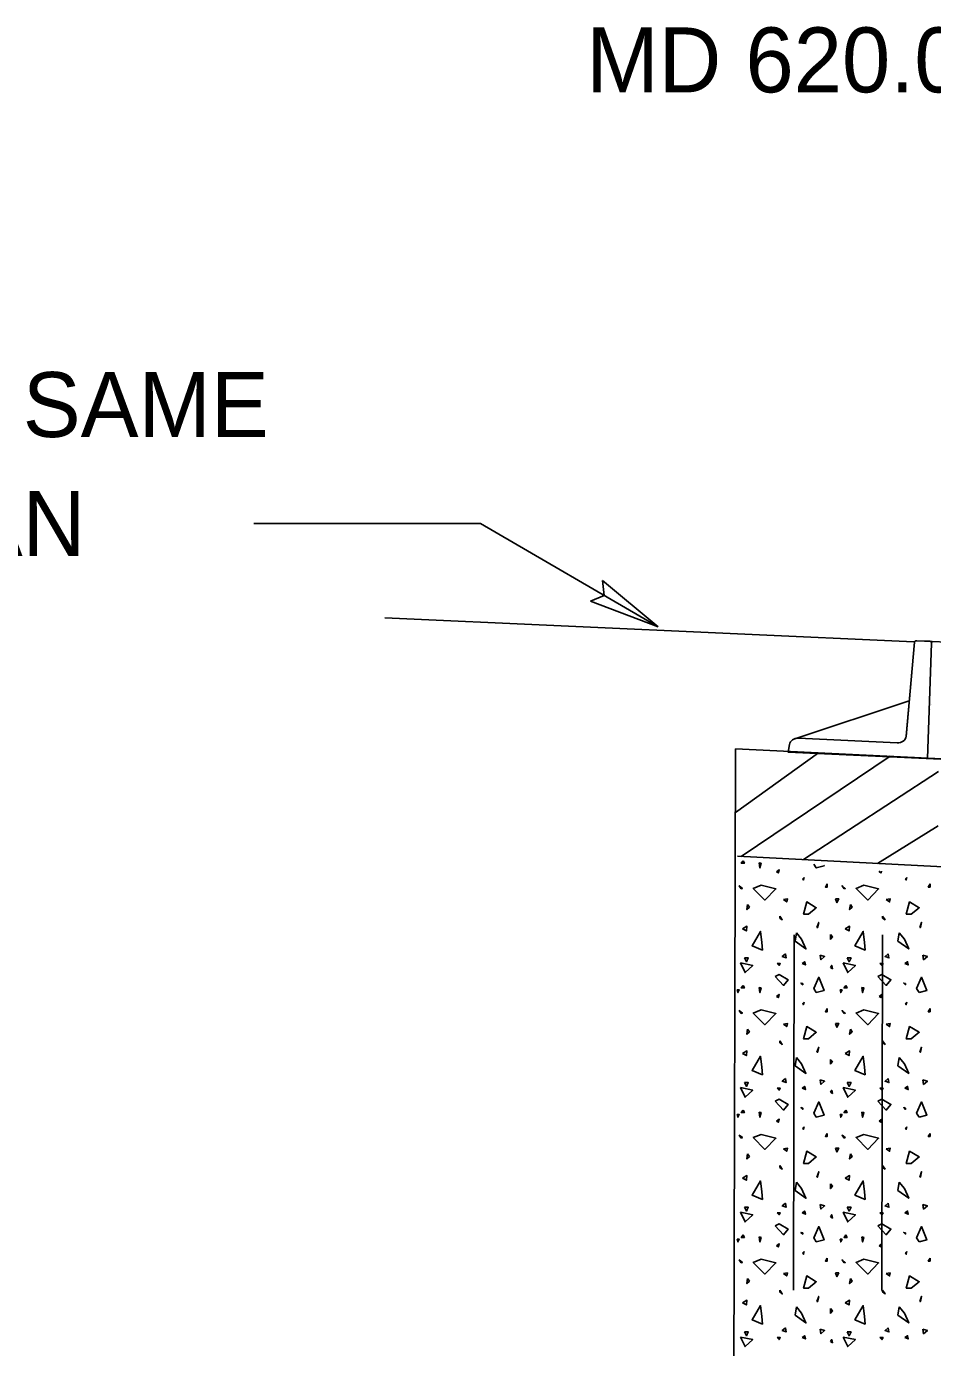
# Model space of a CAD drawing. Extents: x 9.6 to 16.8, y 2.2 to 12.2.
# Drawn here: x 14.196 to 15.034, y 8.202 to 9.423 of the extents above; entities that cross this region are included whole.
import ezdxf

# ---------------------------------------------------------------- set-up
doc = ezdxf.new("R2010")
doc.units = 0
for name, color, linetype in [('DETL-DIMS', 7, 'Continuous'), ('DETL-LINE', 7, 'Continuous'), ('DETL-NOTE', 7, 'Continuous'), ('DETL-PATT', 7, 'Continuous')]:
    doc.layers.add(name, color=color, linetype=linetype)

msp = doc.modelspace()

# ---------------------------------------------------------------- linework, layer by layer
at = {"layer": 'DETL-DIMS'}
for p, q in [((14.6158, 8.9636), (14.4063, 8.9636)), ((14.6158, 8.9636), (14.7799, 8.8683)), ((14.7285, 8.9109), (14.7799, 8.8683)), ((14.7285, 8.9109), (14.7301, 8.8973)), ((14.7175, 8.8919), (14.7301, 8.8973)), ((14.7175, 8.8919), (14.7799, 8.8683))]:
    msp.add_line(p, q, dxfattribs=at)
at = {"layer": 'DETL-LINE'}
for p, q in [((14.5274, 8.8764), (15.0164, 8.8545)), ((15.0169, 8.8539), (15.0092, 8.7671)), ((15.0169, 8.8539), (15.0092, 8.767)), ((15.031, 8.8549), (15.019, 8.8554)), ((15.019, 8.8554), (16.0453, 8.8081)), ((15.0289, 8.7466), (15.0328, 8.8532)), ((15.0121, 8.7999), (14.9062, 8.7648)), ((15.0009, 8.761), (14.9096, 8.7652)), ((15.0009, 8.761), (14.9096, 8.7652)), ((14.8516, 8.7556), (14.847, 6.99)), ((14.8516, 8.7556), (16.1474, 8.6923)), ((14.9001, 8.7525), (14.9013, 8.7596)), ((14.9001, 8.7525), (16.0729, 8.6984)), ((14.8533, 8.6562), (16.1526, 8.5894)), ((14.9058, 8.5837), (14.905, 8.2553)), ((14.9875, 8.5835), (14.9866, 8.2551))]:
    msp.add_line(p, q, dxfattribs=at)
msp.add_lwpolyline([(14.9013, 8.7596), (14.9001, 8.7525), (15.0289, 8.7466), (15.0328, 8.8532)], dxfattribs=at)
for centre, major_axis, start_param, end_param in [((15.0189, 8.8538), (0.00198, -0.00001), 1.521987, 3.073416), ((15.0189, 8.8538), (0.00198, -0.00001), 1.521987, 3.073416), ((15.0309, 8.8532), (0.00198, -0.00001), 6.257027, 7.805172), ((15.0309, 8.8532), (0.00198, -0.00001), 6.257027, 7.805172), ((14.9092, 8.7587), (0.00794, -0.00005), 1.521882, 3.005517), ((14.9092, 8.7587), (0.00794, -0.00005), 1.521987, 3.005517), ((15.0013, 8.7676), (0.00794, -0.00005), 4.663474, 6.226805), ((15.0013, 8.7676), (0.00794, -0.00005), 4.663579, 6.203213)]:
    msp.add_ellipse(centre, major_axis=major_axis, ratio=0.826446, start_param=start_param, end_param=end_param, dxfattribs=at)
at = {"layer": 'DETL-NOTE'}
for p, q in [((15.0318, 8.792), (15.0318, 8.792)), ((15.0331, 8.7967), (15.0331, 8.7967)), ((14.9001, 8.7525), (14.9001, 8.7525)), ((15.0289, 8.7466), (15.0289, 8.7466))]:
    msp.add_line(p, q, dxfattribs=at)
at = {"layer": 'DETL-PATT'}
for p, q in [((14.9282, 8.7519), (14.8515, 8.6967)), ((14.8567, 8.6561), (14.9946, 8.7486)), ((15.039, 8.7345), (14.9144, 8.6531)), ((14.9829, 8.6496), (15.0389, 8.6842))]:
    msp.add_line(p, q, dxfattribs=at)
for points in [[(14.8585, 8.6521), (14.8598, 8.6497), (14.8568, 8.6497)], [(14.8733, 8.6503), (14.874, 8.6455), (14.8751, 8.6497)], [(14.8894, 8.6419), (14.8911, 8.6408), (14.8918, 8.6438)], [(14.9149, 8.6365), (14.9137, 8.6355), (14.9144, 8.6342)], [(15.01, 8.6365), (15.0087, 8.6355), (15.0094, 8.6342)], [(14.8568, 8.626), (14.8579, 8.6265), (14.8549, 8.6289)], [(14.8751, 8.6295), (14.8888, 8.626), (14.8787, 8.6158), (14.8679, 8.6265)], [(14.9363, 8.6306), (14.9346, 8.6277), (14.9363, 8.6277)], [(14.9518, 8.626), (14.9529, 8.6265), (14.95, 8.6289)], [(14.9702, 8.6295), (14.9838, 8.626), (14.9737, 8.6158), (14.9629, 8.6265)], [(15.0313, 8.6306), (15.0296, 8.6277), (15.0313, 8.6277)], [(14.8627, 8.6117), (14.862, 8.6069), (14.8644, 8.6093)], [(14.8959, 8.6164), (14.8989, 8.614), (14.8994, 8.6169)], [(14.9191, 8.6027), (14.9262, 8.6087), (14.9173, 8.614), (14.9144, 8.6027)], [(14.944, 8.6169), (14.9452, 8.6134), (14.947, 8.6169)], [(14.9577, 8.6117), (14.957, 8.6069), (14.9594, 8.6093)], [(14.9909, 8.6164), (14.9939, 8.614), (14.9944, 8.6169)], [(15.014, 8.6027), (15.0213, 8.6087), (15.0124, 8.614), (15.0094, 8.6027)], [(14.8924, 8.601), (14.8924, 8.5991), (14.8947, 8.5975)], [(14.9268, 8.5903), (14.9274, 8.5903), (14.9285, 8.5951)], [(14.9874, 8.601), (14.9874, 8.5991), (14.9898, 8.5975)], [(15.0218, 8.5903), (15.0224, 8.5903), (15.0235, 8.5951)], [(14.8579, 8.5891), (14.8615, 8.5873), (14.862, 8.5915)], [(14.8757, 8.5765), (14.8763, 8.5695), (14.8668, 8.5736), (14.8746, 8.5867)], [(14.9078, 8.5855), (14.9066, 8.5778), (14.9166, 8.5706), (14.9125, 8.5795)], [(14.9392, 8.5838), (14.9392, 8.5795), (14.9411, 8.5819)], [(14.9529, 8.5891), (14.9565, 8.5873), (14.957, 8.5915)], [(14.9707, 8.5765), (14.9713, 8.5695), (14.9618, 8.5736), (14.9696, 8.5867)], [(15.0027, 8.5855), (15.0016, 8.5778), (15.0116, 8.5706), (15.0076, 8.5795)], [(14.8561, 8.5576), (14.8603, 8.5487), (14.8674, 8.5553)], [(14.8598, 8.5623), (14.8615, 8.5588), (14.8633, 8.5623)], [(14.8977, 8.566), (14.8947, 8.5636), (14.8983, 8.5623)], [(14.9131, 8.5571), (14.9161, 8.5558), (14.9155, 8.5588)], [(14.9298, 8.5647), (14.9304, 8.5606), (14.9339, 8.5636)], [(14.9511, 8.5576), (14.9553, 8.5487), (14.9624, 8.5553)], [(14.9547, 8.5623), (14.9565, 8.5588), (14.9583, 8.5623)], [(14.9927, 8.566), (14.9898, 8.5636), (14.9933, 8.5623)], [(15.0081, 8.5571), (15.0111, 8.5558), (15.0105, 8.5588)], [(15.0248, 8.5647), (15.0253, 8.5606), (15.0289, 8.5636)], [(14.8881, 8.5452), (14.8959, 8.5369), (14.9001, 8.5421), (14.8918, 8.5469)], [(14.89, 8.5571), (14.8918, 8.5553), (14.8929, 8.5571)], [(14.9392, 8.5534), (14.9411, 8.5523), (14.9405, 8.5553)], [(14.9831, 8.5452), (14.9909, 8.5369), (14.9951, 8.5421), (14.9868, 8.5469)], [(14.985, 8.5571), (14.9868, 8.5553), (14.9879, 8.5571)], [(14.8585, 8.5369), (14.8598, 8.5345), (14.8568, 8.5345)], [(14.8733, 8.5351), (14.874, 8.5303), (14.8751, 8.5345)], [(14.9137, 8.5386), (14.912, 8.5391), (14.9137, 8.5375)], [(14.9262, 8.5303), (14.9333, 8.5321), (14.9285, 8.5445), (14.9238, 8.5339)], [(14.9535, 8.5369), (14.9547, 8.5345), (14.9518, 8.5345)], [(14.9683, 8.5351), (14.969, 8.5303), (14.9702, 8.5345)], [(15.0087, 8.5386), (15.007, 8.5391), (15.0087, 8.5375)], [(15.0213, 8.5303), (15.0283, 8.5321), (15.0235, 8.5445), (15.0189, 8.5339)], [(14.8531, 8.5327), (14.8537, 8.5303), (14.8549, 8.5327)], [(14.8894, 8.5267), (14.8911, 8.5256), (14.8918, 8.5285)], [(14.9149, 8.5214), (14.9137, 8.5202), (14.9144, 8.519)], [(14.9481, 8.5327), (14.9487, 8.5303), (14.95, 8.5327)], [(14.9844, 8.5267), (14.9861, 8.5256), (14.9868, 8.5285)], [(15.01, 8.5214), (15.0087, 8.5202), (15.0094, 8.519)], [(14.8568, 8.5108), (14.8579, 8.5113), (14.8549, 8.5137)], [(14.8751, 8.5143), (14.8888, 8.5108), (14.8787, 8.5006), (14.8679, 8.5113)], [(14.9363, 8.5155), (14.9346, 8.5125), (14.9363, 8.5125)], [(14.9518, 8.5108), (14.9529, 8.5113), (14.95, 8.5137)], [(14.9702, 8.5143), (14.9838, 8.5108), (14.9737, 8.5006), (14.9629, 8.5113)], [(15.0313, 8.5155), (15.0296, 8.5125), (15.0313, 8.5125)], [(14.8959, 8.5012), (14.8989, 8.4988), (14.8994, 8.5017)], [(14.9191, 8.4875), (14.9262, 8.4936), (14.9173, 8.4988), (14.9144, 8.4875)], [(14.944, 8.5017), (14.9452, 8.4982), (14.947, 8.5017)], [(14.9909, 8.5012), (14.9939, 8.4988), (14.9944, 8.5017)], [(15.014, 8.4875), (15.0213, 8.4936), (15.0124, 8.4988), (15.0094, 8.4875)], [(14.8627, 8.4965), (14.862, 8.4917), (14.8644, 8.4941)], [(14.8924, 8.4858), (14.8924, 8.484), (14.8947, 8.4823)], [(14.9577, 8.4965), (14.957, 8.4917), (14.9594, 8.4941)], [(14.9874, 8.4858), (14.9874, 8.484), (14.9898, 8.4823)], [(14.8579, 8.4739), (14.8615, 8.4721), (14.862, 8.4763)], [(14.9268, 8.4751), (14.9274, 8.4751), (14.9285, 8.4798)], [(14.9529, 8.4739), (14.9565, 8.4721), (14.957, 8.4763)], [(15.0218, 8.4751), (15.0224, 8.4751), (15.0235, 8.4798)], [(14.8757, 8.4614), (14.8763, 8.4543), (14.8668, 8.4584), (14.8746, 8.4715)], [(14.9078, 8.4703), (14.9066, 8.4626), (14.9166, 8.4555), (14.9125, 8.4643)], [(14.9392, 8.4685), (14.9392, 8.4643), (14.9411, 8.4667)], [(14.9707, 8.4614), (14.9713, 8.4543), (14.9618, 8.4584), (14.9696, 8.4715)], [(15.0027, 8.4703), (15.0016, 8.4626), (15.0116, 8.4555), (15.0076, 8.4643)], [(14.8977, 8.4508), (14.8947, 8.4484), (14.8983, 8.4471)], [(14.9298, 8.4495), (14.9304, 8.4454), (14.9339, 8.4484)], [(14.9927, 8.4508), (14.9898, 8.4484), (14.9933, 8.4471)], [(15.0248, 8.4495), (15.0253, 8.4454), (15.0289, 8.4484)], [(14.8561, 8.4424), (14.8603, 8.4336), (14.8674, 8.44)], [(14.8598, 8.4471), (14.8615, 8.4436), (14.8633, 8.4471)], [(14.89, 8.4419), (14.8918, 8.44), (14.8929, 8.4419)], [(14.9131, 8.4419), (14.9161, 8.4406), (14.9155, 8.4436)], [(14.9392, 8.4382), (14.9411, 8.4371), (14.9405, 8.44)], [(14.9511, 8.4424), (14.9553, 8.4336), (14.9624, 8.44)], [(14.9547, 8.4471), (14.9565, 8.4436), (14.9583, 8.4471)], [(14.985, 8.4419), (14.9868, 8.44), (14.9879, 8.4419)], [(15.0081, 8.4419), (15.0111, 8.4406), (15.0105, 8.4436)], [(14.8881, 8.43), (14.8959, 8.4217), (14.9001, 8.4269), (14.8918, 8.4317)], [(14.9137, 8.4234), (14.912, 8.424), (14.9137, 8.4223)], [(14.9262, 8.4151), (14.9333, 8.4169), (14.9285, 8.4293), (14.9238, 8.4187)], [(14.9831, 8.43), (14.9909, 8.4217), (14.9951, 8.4269), (14.9868, 8.4317)], [(15.0087, 8.4234), (15.007, 8.424), (15.0087, 8.4223)], [(15.0213, 8.4151), (15.0283, 8.4169), (15.0235, 8.4293), (15.0189, 8.4187)], [(14.8531, 8.4175), (14.8537, 8.4151), (14.8549, 8.4175)], [(14.8585, 8.4217), (14.8598, 8.4193), (14.8568, 8.4193)], [(14.8733, 8.4198), (14.874, 8.4151), (14.8751, 8.4193)], [(14.8894, 8.4115), (14.8911, 8.4104), (14.8918, 8.4134)], [(14.9481, 8.4175), (14.9487, 8.4151), (14.95, 8.4175)], [(14.9535, 8.4217), (14.9547, 8.4193), (14.9518, 8.4193)], [(14.9683, 8.4198), (14.969, 8.4151), (14.9702, 8.4193)], [(14.9844, 8.4115), (14.9861, 8.4104), (14.9868, 8.4134)], [(14.8751, 8.3991), (14.8888, 8.3956), (14.8787, 8.3854), (14.8679, 8.3962)], [(14.9149, 8.4062), (14.9137, 8.405), (14.9144, 8.4038)], [(14.9363, 8.4002), (14.9346, 8.3973), (14.9363, 8.3973)], [(14.9702, 8.3991), (14.9838, 8.3956), (14.9737, 8.3854), (14.9629, 8.3962)], [(15.01, 8.4062), (15.0087, 8.405), (15.0094, 8.4038)], [(15.0313, 8.4002), (15.0296, 8.3973), (15.0313, 8.3973)], [(14.8568, 8.3956), (14.8579, 8.3962), (14.8549, 8.3985)], [(14.9518, 8.3956), (14.9529, 8.3962), (14.95, 8.3985)], [(14.8627, 8.3813), (14.862, 8.3765), (14.8644, 8.3789)], [(14.8959, 8.386), (14.8989, 8.3836), (14.8994, 8.3865)], [(14.9191, 8.3723), (14.9262, 8.3784), (14.9173, 8.3836), (14.9144, 8.3723)], [(14.944, 8.3865), (14.9452, 8.383), (14.947, 8.3865)], [(14.9577, 8.3813), (14.957, 8.3765), (14.9594, 8.3789)], [(14.9909, 8.386), (14.9939, 8.3836), (14.9944, 8.3865)], [(15.014, 8.3723), (15.0213, 8.3784), (15.0124, 8.3836), (15.0094, 8.3723)], [(14.8924, 8.3706), (14.8924, 8.3687), (14.8947, 8.3671)], [(14.9268, 8.3598), (14.9274, 8.3598), (14.9285, 8.3647)], [(14.9874, 8.3706), (14.9874, 8.3687), (14.9898, 8.3671)], [(15.0218, 8.3598), (15.0224, 8.3598), (15.0235, 8.3647)], [(14.8579, 8.3587), (14.8615, 8.3569), (14.862, 8.3611)], [(14.8757, 8.3462), (14.8763, 8.3391), (14.8668, 8.3432), (14.8746, 8.3563)], [(14.9078, 8.3551), (14.9066, 8.3475), (14.9166, 8.3402), (14.9125, 8.3491)], [(14.9392, 8.3534), (14.9392, 8.3491), (14.9411, 8.3515)], [(14.9529, 8.3587), (14.9565, 8.3569), (14.957, 8.3611)], [(14.9707, 8.3462), (14.9713, 8.3391), (14.9618, 8.3432), (14.9696, 8.3563)], [(15.0027, 8.3551), (15.0016, 8.3475), (15.0116, 8.3402), (15.0076, 8.3491)], [(14.8561, 8.3273), (14.8603, 8.3184), (14.8674, 8.3249)], [(14.8598, 8.3319), (14.8615, 8.3284), (14.8633, 8.3319)], [(14.89, 8.3267), (14.8918, 8.3249), (14.8929, 8.3267)], [(14.8977, 8.3356), (14.8947, 8.3332), (14.8983, 8.3319)], [(14.9131, 8.3267), (14.9161, 8.3254), (14.9155, 8.3284)], [(14.9298, 8.3343), (14.9304, 8.3302), (14.9339, 8.3332)], [(14.9511, 8.3273), (14.9553, 8.3184), (14.9624, 8.3249)], [(14.9547, 8.3319), (14.9565, 8.3284), (14.9583, 8.3319)], [(14.985, 8.3267), (14.9868, 8.3249), (14.9879, 8.3267)], [(14.9927, 8.3356), (14.9898, 8.3332), (14.9933, 8.3319)], [(15.0081, 8.3267), (15.0111, 8.3254), (15.0105, 8.3284)], [(15.0248, 8.3343), (15.0253, 8.3302), (15.0289, 8.3332)], [(14.8881, 8.3148), (14.8959, 8.3065), (14.9001, 8.3117), (14.8918, 8.3165)], [(14.9262, 8.2998), (14.9333, 8.3017), (14.9285, 8.3141), (14.9238, 8.3035)], [(14.9392, 8.323), (14.9411, 8.3219), (14.9405, 8.3249)], [(14.9831, 8.3148), (14.9909, 8.3065), (14.9951, 8.3117), (14.9868, 8.3165)], [(15.0213, 8.2998), (15.0283, 8.3017), (15.0235, 8.3141), (15.0189, 8.3035)], [(14.8531, 8.3023), (14.8537, 8.2998), (14.8549, 8.3023)], [(14.8585, 8.3065), (14.8598, 8.3041), (14.8568, 8.3041)], [(14.8733, 8.3047), (14.874, 8.2998), (14.8751, 8.3041)], [(14.9137, 8.3082), (14.912, 8.3087), (14.9137, 8.3071)], [(14.9481, 8.3023), (14.9487, 8.2998), (14.95, 8.3023)], [(14.9535, 8.3065), (14.9547, 8.3041), (14.9518, 8.3041)], [(14.9683, 8.3047), (14.969, 8.2998), (14.9702, 8.3041)], [(15.0087, 8.3082), (15.007, 8.3087), (15.0087, 8.3071)], [(14.8894, 8.2963), (14.8911, 8.2952), (14.8918, 8.2982)], [(14.9149, 8.291), (14.9137, 8.2898), (14.9144, 8.2885)], [(14.9844, 8.2963), (14.9861, 8.2952), (14.9868, 8.2982)], [(15.01, 8.291), (15.0087, 8.2898), (15.0094, 8.2885)], [(14.8568, 8.2804), (14.8579, 8.2809), (14.8549, 8.2833)], [(14.8751, 8.2839), (14.8888, 8.2804), (14.8787, 8.2702), (14.8679, 8.2809)], [(14.9363, 8.285), (14.9346, 8.2821), (14.9363, 8.2821)], [(14.9518, 8.2804), (14.9529, 8.2809), (14.95, 8.2833)], [(14.9702, 8.2839), (14.9838, 8.2804), (14.9737, 8.2702), (14.9629, 8.2809)], [(15.0313, 8.285), (15.0296, 8.2821), (15.0313, 8.2821)], [(14.8627, 8.2661), (14.862, 8.2613), (14.8644, 8.2637)], [(14.8959, 8.2708), (14.8989, 8.2684), (14.8994, 8.2713)], [(14.9191, 8.2571), (14.9262, 8.2631), (14.9173, 8.2684), (14.9144, 8.2571)], [(14.944, 8.2713), (14.9452, 8.2678), (14.947, 8.2713)], [(14.9577, 8.2661), (14.957, 8.2613), (14.9594, 8.2637)], [(14.9909, 8.2708), (14.9939, 8.2684), (14.9944, 8.2713)], [(15.014, 8.2571), (15.0213, 8.2631), (15.0124, 8.2684), (15.0094, 8.2571)], [(14.8924, 8.2554), (14.8924, 8.2536), (14.8947, 8.2518)], [(14.9874, 8.2554), (14.9874, 8.2536), (14.9898, 8.2518)], [(14.8579, 8.2435), (14.8615, 8.2417), (14.862, 8.2459)], [(14.8757, 8.231), (14.8763, 8.2239), (14.8668, 8.228), (14.8746, 8.2411)], [(14.9268, 8.2447), (14.9274, 8.2447), (14.9285, 8.2495)], [(14.9529, 8.2435), (14.9565, 8.2417), (14.957, 8.2459)], [(14.9707, 8.231), (14.9713, 8.2239), (14.9618, 8.228), (14.9696, 8.2411)], [(15.0218, 8.2447), (15.0224, 8.2447), (15.0235, 8.2495)], [(14.9078, 8.2398), (14.9066, 8.2322), (14.9166, 8.225), (14.9125, 8.2339)], [(14.9392, 8.2382), (14.9392, 8.2339), (14.9411, 8.2363)], [(15.0027, 8.2398), (15.0016, 8.2322), (15.0116, 8.225), (15.0076, 8.2339)], [(14.8598, 8.2167), (14.8615, 8.2132), (14.8633, 8.2167)], [(14.8977, 8.2204), (14.8947, 8.218), (14.8983, 8.2167)], [(14.9298, 8.2191), (14.9304, 8.215), (14.9339, 8.218)], [(14.9547, 8.2167), (14.9565, 8.2132), (14.9583, 8.2167)], [(14.9927, 8.2204), (14.9898, 8.218), (14.9933, 8.2167)], [(15.0248, 8.2191), (15.0253, 8.215), (15.0289, 8.218)], [(14.8561, 8.212), (14.8603, 8.2031), (14.8674, 8.2096)], [(14.89, 8.2115), (14.8918, 8.2096), (14.8929, 8.2115)], [(14.9131, 8.2115), (14.9161, 8.2102), (14.9155, 8.2132)], [(14.9392, 8.2078), (14.9411, 8.2067), (14.9405, 8.2096)], [(14.9511, 8.212), (14.9553, 8.2031), (14.9624, 8.2096)], [(14.985, 8.2115), (14.9868, 8.2096), (14.9879, 8.2115)], [(15.0081, 8.2115), (15.0111, 8.2102), (15.0105, 8.2132)]]:
    msp.add_lwpolyline(points, close=True, dxfattribs=at)
for points in [[(14.924, 8.6489), (14.9262, 8.6455), (14.9333, 8.6473), (14.9331, 8.6479)], [(14.9852, 8.6425), (14.9844, 8.6419), (14.9861, 8.6408), (14.9865, 8.6424)]]:
    msp.add_lwpolyline(points, dxfattribs=at)

# ---------------------------------------------------------------- texts
at = {"layer": 'DETL-NOTE'}
for s, p in [('MD 620.02-01', (14.7136, 9.3621)), ('GRATE SLOPE SAME', (13.6041, 9.0436)), ('AS GUTTER PAN', (13.6041, 8.9336))]:
    msp.add_text(s, height=0.06, dxfattribs=at).set_placement(p)

doc.saveas('drawing.dxf')
